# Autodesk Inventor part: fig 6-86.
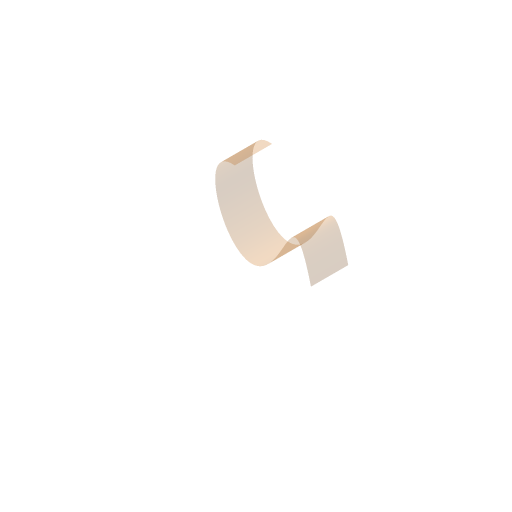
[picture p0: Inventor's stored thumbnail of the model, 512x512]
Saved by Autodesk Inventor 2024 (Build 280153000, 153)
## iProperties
Shininess: 64.0
Length Units: 11269
Angle Units: 11279
Time Units: 11290
Mass Units: 11283
Length Display Precision: 3
Angle Display Precision: 2
Compacted: True
Part Number: fig 6-86.
Document SubType Name: Modeling
Created: 2002-12
Designer: deepak
Density: 1 g/cm^3
Material: Generic
Appearance: Default
Density: 0.0
Volumn: 0.0
Area: 0.0
PropertySet Name: Model Information
Control State: 0
Master: False
Checked Out: False
Author: deepak
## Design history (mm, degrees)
sketch "Sketch1"
  geometry: 5 further points
  constraints: 5 other
extrude_surface "ExtrusionSrf1" sketch "Sketch1" dims "d0" = 20, "d1" = 0
body "Srf1"
